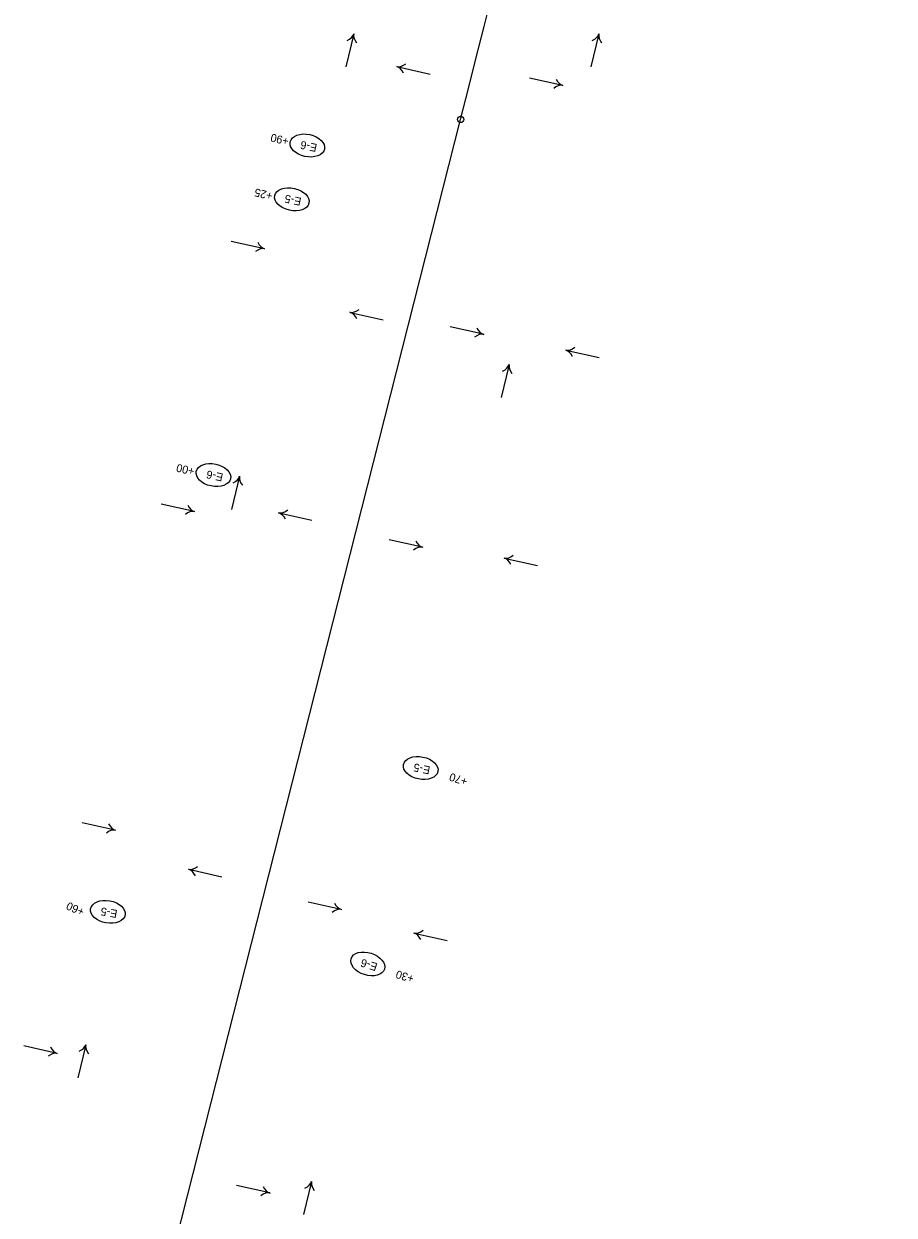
# Model space of a CAD drawing. Extents: x 669236 to 673912, y 735758 to 754788.
# Drawn here: x 669839 to 670518, y 738615 to 739545 of the extents above; entities that cross this region are included whole.
import ezdxf

# ---------------------------------------------------------------- set-up
doc = ezdxf.new("R2010")
doc.units = 0
for name, color, linetype in [('Default', 7, 'Continuous'), ('Prop_Horiz Alignment', 7, 'Continuous'), ('R_Erosion_3', 7, 'Continuous'), ('R_Flow Arrows', 7, 'Continuous')]:
    doc.layers.add(name, color=color, linetype=linetype)

msp = doc.modelspace()

# ---------------------------------------------------------------- linework, layer by layer
at = {"layer": 'Default'}
msp.add_line((669901.33, 738373), (670179.59, 739470.12), dxfattribs=at)
msp.add_arc((647964.63, 745104.34), 22918.31, 345.768552, 349.761052, dxfattribs=at)
at = {"layer": 'Prop_Horiz Alignment'}
msp.add_circle((670179.59, 739470.12), 2.5, dxfattribs=at)
at = {"layer": 'R_Erosion_3'}
for centre, major_axis in [((670059.96, 739449.72), (-13.39, 2.87)), ((670047.86, 739407.73), (-13.37, 2.96)), ((669986.63, 739192.49), (-13.39, 2.87)), ((670148.44, 738963.75), (-13.41, 2.78)), ((669904.28, 738851.47), (-13.49, 2.4)), ((670107.12, 738810.81), (-13.07, 4.1))]:
    msp.add_ellipse(centre, major_axis=major_axis, ratio=0.638788, dxfattribs=at)
at = {"layer": 'R_Flow Arrows'}
for p, q in [((670096.18, 739536.83), (670089.91, 739511.02)), ((670287.47, 739536.83), (670281.21, 739511.02)), ((670129.87, 739511.3), (670155.8, 739505.53)), ((670259.26, 739496.64), (670233.33, 739502.41)), ((670026.45, 739369.15), (670000.52, 739374.92)), ((670093.3, 739319.48), (670119.23, 739313.71)), ((670197.44, 739302.34), (670171.51, 739308.12)), ((670261.76, 739289.91), (670287.69, 739284.14)), ((670217.46, 739278.77), (670211.2, 739252.96)), ((670007.1, 739191.49), (670000.83, 739165.68)), ((669971.76, 739163.92), (669945.83, 739169.69)), ((670037.65, 739162.93), (670063.57, 739157.16)), ((670149.82, 739136.08), (670123.89, 739141.85)), ((670213.67, 739127.61), (670239.6, 739121.84)), ((669910.08, 738915.23), (669884.15, 738921)), ((669967.36, 738884.69), (669993.29, 738878.92)), ((670086.43, 738853.36), (670060.5, 738859.14)), ((670143.24, 738834.85), (670169.17, 738829.07)), ((669864.61, 738740.99), (669838.68, 738746.76)), ((669887.03, 738747.69), (669880.76, 738721.88)), ((670030.66, 738632.02), (670004.73, 738637.79)), ((670063.2, 738640.95), (670056.93, 738615.14))]:
    msp.add_line(p, q, dxfattribs=at)
for centre, major_axis, start_param, end_param in [((670076.7, 739542.02), (19.59, -4.76), 5.662936, 6.259934), ((670115.83, 739532.33), (-19.59, 4.76), 0.023252, 0.620249), ((670267.99, 739542.02), (19.59, -4.76), 5.662936, 6.259934), ((670307.12, 739532.33), (-19.59, 4.76), 0.023252, 0.620249), ((670125.06, 739491.72), (4.38, 19.68), 5.662936, 6.259934), ((670133.99, 739531.03), (-4.38, -19.68), 0.023252, 0.620249), ((670264.07, 739516.22), (-4.38, -19.68), 5.662936, 6.259934), ((670255.14, 739476.9), (4.38, 19.68), 0.023252, 0.620249), ((670022.33, 739349.42), (4.38, 19.68), 0.023252, 0.620249), ((670031.26, 739388.73), (-4.38, -19.68), 5.662936, 6.259934), ((670097.42, 739339.22), (-4.38, -19.68), 0.023252, 0.620249), ((670088.49, 739299.91), (4.38, 19.68), 5.662936, 6.259934), ((670202.25, 739321.92), (-4.38, -19.68), 5.662936, 6.259934), ((670193.32, 739282.61), (4.38, 19.68), 0.023252, 0.620249), ((670256.96, 739270.33), (4.38, 19.68), 5.662936, 6.259934), ((670265.89, 739309.64), (-4.38, -19.68), 0.023252, 0.620249), ((670197.98, 739283.96), (19.59, -4.76), 5.662936, 6.259934), ((670237.11, 739274.27), (-19.59, 4.76), 0.023252, 0.620249), ((669987.61, 739196.67), (19.59, -4.76), 5.662936, 6.259934), ((670026.75, 739186.99), (-19.59, 4.76), 0.023252, 0.620249), ((669967.64, 739144.19), (4.38, 19.68), 0.023252, 0.620249), ((669976.56, 739183.5), (-4.38, -19.68), 5.662936, 6.259934), ((670041.77, 739182.66), (-4.38, -19.68), 0.023252, 0.620249), ((670032.84, 739143.35), (4.38, 19.68), 5.662936, 6.259934), ((670145.7, 739116.35), (4.38, 19.68), 0.023252, 0.620249), ((670154.63, 739155.66), (-4.38, -19.68), 5.662936, 6.259934), ((670208.86, 739108.04), (4.38, 19.68), 5.662936, 6.259934), ((670217.79, 739147.35), (-4.38, -19.68), 0.023252, 0.620249), ((669905.96, 738895.49), (4.38, 19.68), 0.023252, 0.620249), ((669914.89, 738934.8), (-4.38, -19.68), 5.662936, 6.259934), ((669962.55, 738865.11), (4.38, 19.68), 5.662936, 6.259934), ((669971.48, 738904.42), (-4.38, -19.68), 0.023252, 0.620249), ((670091.24, 738872.94), (-4.38, -19.68), 5.662936, 6.259934), ((670082.31, 738833.63), (4.38, 19.68), 0.023252, 0.620249), ((670138.43, 738815.27), (4.38, 19.68), 5.662936, 6.259934), ((670147.36, 738854.58), (-4.38, -19.68), 0.023252, 0.620249), ((669869.42, 738760.57), (-4.38, -19.68), 5.662936, 6.259934), ((669867.55, 738752.88), (19.59, -4.76), 5.662936, 6.259934), ((669906.68, 738743.19), (-19.59, 4.76), 0.023252, 0.620249), ((669860.49, 738721.25), (4.38, 19.68), 0.023252, 0.620249), ((670035.46, 738651.6), (-4.38, -19.68), 5.662936, 6.259934), ((670043.72, 738646.14), (19.59, -4.76), 5.662936, 6.259934), ((670082.85, 738636.46), (-19.59, 4.76), 0.023252, 0.620249), ((670026.54, 738612.29), (4.38, 19.68), 0.023252, 0.620249)]:
    msp.add_ellipse(centre, major_axis=major_axis, ratio=0.5625, start_param=start_param, end_param=end_param, dxfattribs=at)

# ---------------------------------------------------------------- texts
at = {"layer": 'R_Erosion_3'}
for s, rotation, p in [('+90', 166.60301, (670045.96, 739455.82)), ('E-6', 167.90331, (670067.99, 739450.73)), ('+25', 166.60301, (670033.35, 739413.07)), ('E-5', 167.53366, (670055.72, 739408.72)), ('+00', 166.60301, (669972.38, 739198.09)), ('E-6', 167.90331, (669994.66, 739193.5)), ('E-5', 168.28076, (670156.29, 738964.84)), ('+70', 162.30814, (670185.51, 738955.78)), ('+60', 155.86613, (669886.56, 738853.7)), ('E-5', 169.91915, (669912.09, 738852.79)), ('E-6', 162.56684, (670115.2, 738811.07)), ('+30', 163.09173, (670143.75, 738801.86))]:
    msp.add_text(s, height=6.25, rotation=rotation, dxfattribs=at).set_placement(p)

doc.saveas('drawing.dxf')
